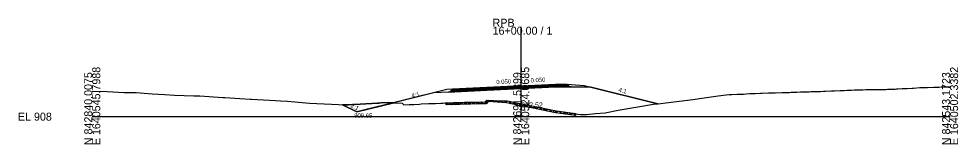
# Model space of a CAD drawing. Extents: x -26 to 1641030, y -10 to 842962.
# Drawn here: x -25.7 to 302.8, y 5990.3 to 6034.4 of the extents above; entities that cross this region are included whole.
import ezdxf

# ---------------------------------------------------------------- set-up
doc = ezdxf.new("R2010")
doc.units = 0
for name, color, linetype in [('Exist Cross Section Cell', 7, 'Continuous'), ('Exist XS Center Line Elevation Label', 7, 'Continuous'), ('Exist XS Ground Line', 7, 'Continuous'), ('Prop CMT Pvmt Course 1', 7, 'Continuous'), ('Prop CMT Pvmt Course 2', 7, 'Continuous'), ('Prop CMT Pvmt Course 3', 7, 'Continuous'), ('Prop CMT Pvmt Surface', 7, 'Continuous'), ('Prop CMT Pvmt Surface Shoulder', 7, 'Continuous'), ('Prop CMT Shld Paved Course 1', 7, 'Continuous'), ('Prop CMT Shld Paved Course 2', 7, 'Continuous'), ('Prop CMT Shld Paved Course 3', 7, 'Continuous'), ('Prop CMT Slope Grass', 7, 'Continuous'), ('Prop CMT Subgrade Earthwork', 7, 'Continuous'), ('Prop XS Ditch Standard Text', 7, 'Continuous'), ('Prop XS SE Text', 7, 'Continuous'), ('Prop XS Side Slope Text', 7, 'Continuous'), ('Prop XS Undercut Exc', 7, 'Continuous'), ('Scratch_Level_2', 7, 'Continuous'), ('Scratch_Level_3', 7, 'Continuous')]:
    doc.layers.add(name, color=color, linetype=linetype)

msp = doc.modelspace()

# ---------------------------------------------------------------- linework, layer by layer
at = {"layer": 'Exist Cross Section Cell'}
for p, q in [((150, 6000), (150, 6031.55)), ((0, 6000), (150, 6000)), ((150, 6000), (300, 6000))]:
    msp.add_line(p, q, dxfattribs=at)
at = {"layer": 'Exist XS Ground Line'}
for p, q in [((0, 6008.93), (5.2, 6008.82)), ((253.94, 6008.84), (254.69, 6008.87)), ((254.69, 6008.87), (255.74, 6008.92)), ((255.74, 6008.92), (256.47, 6008.95)), ((256.47, 6008.95), (258.57, 6009.04)), ((258.57, 6009.04), (258.99, 6009.06)), ((258.99, 6009.06), (259.55, 6009.08)), ((259.55, 6009.08), (261.52, 6009.17)), ((261.52, 6009.17), (262.98, 6009.23)), ((262.98, 6009.23), (264.04, 6009.28)), ((264.04, 6009.28), (265.47, 6009.32)), ((265.47, 6009.32), (266.57, 6009.36)), ((266.57, 6009.36), (268.43, 6009.43)), ((268.43, 6009.43), (269.1, 6009.46)), ((269.1, 6009.46), (269.53, 6009.46)), ((269.53, 6009.46), (270.59, 6009.47)), ((270.59, 6009.47), (271.62, 6009.48)), ((271.62, 6009.48), (273, 6009.5)), ((273, 6009.5), (274.35, 6009.52)), ((274.35, 6009.52), (276.68, 6009.57)), ((276.68, 6009.57), (277.54, 6009.58)), ((277.54, 6009.58), (278.16, 6009.6)), ((278.16, 6009.6), (279.07, 6009.63)), ((279.07, 6009.63), (280.84, 6009.69)), ((280.84, 6009.69), (281.29, 6009.71)), ((281.29, 6009.71), (281.73, 6009.74)), ((281.73, 6009.74), (283.23, 6009.82)), ((283.23, 6009.82), (284.26, 6009.87)), ((284.26, 6009.87), (285.02, 6009.91)), ((285.02, 6009.91), (286.78, 6010.01)), ((286.78, 6010.01), (287.23, 6010.04)), ((287.23, 6010.04), (289.4, 6010.17)), ((289.4, 6010.17), (289.73, 6010.17)), ((289.73, 6010.17), (291.45, 6010.24)), ((291.45, 6010.24), (292.11, 6010.26)), ((292.11, 6010.26), (294.36, 6010.34)), ((294.36, 6010.34), (296.04, 6010.39)), ((296.04, 6010.39), (296.89, 6010.42)), ((296.89, 6010.42), (298.03, 6010.46)), ((298.03, 6010.46), (299.42, 6010.5)), ((299.42, 6010.5), (300, 6010.52)), ((5.2, 6008.82), (11.13, 6008.51)), ((11.13, 6008.51), (15.3, 6008.45)), ((15.3, 6008.45), (20.91, 6008)), ((20.91, 6008), (25.41, 6007.81)), ((25.41, 6007.81), (28.76, 6007.49)), ((28.76, 6007.49), (35.52, 6007.35)), ((35.52, 6007.35), (37.58, 6007.25)), ((37.58, 6007.25), (45.63, 6006.72)), ((45.63, 6006.72), (46.4, 6006.68)), ((46.4, 6006.68), (51.65, 6006.35)), ((51.65, 6006.35), (55.21, 6006.12)), ((55.21, 6006.12), (55.73, 6006.09)), ((55.73, 6006.09), (64.03, 6005.67)), ((64.03, 6005.67), (65.84, 6005.55)), ((137.43, 6005.18), (138.04, 6005.75)), ((138.04, 6005.75), (140.43, 6005.68)), ((140.43, 6005.68), (145.11, 6005.5)), ((201.47, 6004.97), (210, 6006.04)), ((210, 6006.04), (214.05, 6006.6)), ((214.05, 6006.6), (218.84, 6007.27)), ((218.84, 6007.27), (221.74, 6007.67)), ((221.74, 6007.67), (222.77, 6007.74)), ((222.77, 6007.74), (223.62, 6007.79)), ((223.62, 6007.79), (225.52, 6007.87)), ((225.52, 6007.87), (226.14, 6007.89)), ((226.14, 6007.89), (227.72, 6007.94)), ((227.72, 6007.94), (228.67, 6008.01)), ((228.67, 6008.01), (229.92, 6008.09)), ((229.92, 6008.09), (231.2, 6008.14)), ((231.2, 6008.14), (231.83, 6008.16)), ((231.83, 6008.16), (233.72, 6008.22)), ((233.72, 6008.22), (234.33, 6008.24)), ((234.33, 6008.24), (236.54, 6008.3)), ((236.54, 6008.3), (238.83, 6008.36)), ((238.83, 6008.36), (241.3, 6008.43)), ((241.3, 6008.43), (241.8, 6008.44)), ((241.8, 6008.44), (243.81, 6008.5)), ((243.81, 6008.5), (244.4, 6008.54)), ((244.4, 6008.54), (245.3, 6008.56)), ((245.3, 6008.56), (246.36, 6008.6)), ((246.36, 6008.6), (247.71, 6008.65)), ((247.71, 6008.65), (248.88, 6008.69)), ((248.88, 6008.69), (250.67, 6008.74)), ((250.67, 6008.74), (251.41, 6008.77)), ((251.41, 6008.77), (253.63, 6008.83)), ((253.63, 6008.83), (253.94, 6008.84)), ((65.84, 6005.55), (68.28, 6005.38)), ((68.28, 6005.38), (75.95, 6004.78)), ((75.95, 6004.78), (83.7, 6004.4)), ((83.7, 6004.4), (88.61, 6004.14)), ((88.61, 6004.14), (89.63, 6004.15)), ((89.63, 6004.15), (99.71, 6004.74)), ((99.71, 6004.74), (100.24, 6004.77)), ((100.24, 6004.77), (100.93, 6004.81)), ((100.93, 6004.81), (103.76, 6004.97)), ((103.76, 6004.97), (104.99, 6004.9)), ((104.99, 6004.9), (105.73, 6004.85)), ((105.73, 6004.85), (108.38, 6004.68)), ((108.38, 6004.68), (108.99, 6004.16)), ((108.99, 6004.16), (110.81, 6004.21)), ((110.81, 6004.21), (112.44, 6004.31)), ((112.44, 6004.31), (114.5, 6004.42)), ((114.5, 6004.42), (114.97, 6004.44)), ((114.97, 6004.44), (117.68, 6004.56)), ((117.68, 6004.56), (120.02, 6004.65)), ((120.02, 6004.65), (121.93, 6004.73)), ((121.93, 6004.73), (122.55, 6004.76)), ((122.55, 6004.76), (123.35, 6004.79)), ((123.35, 6004.79), (123.76, 6004.81)), ((123.76, 6004.81), (125.08, 6004.86)), ((125.08, 6004.86), (126.34, 6004.91)), ((126.34, 6004.91), (127.6, 6004.95)), ((127.6, 6004.95), (128.54, 6004.98)), ((128.54, 6004.98), (130.13, 6005.03)), ((130.13, 6005.03), (132.27, 6005.07)), ((132.27, 6005.07), (132.66, 6005.08)), ((132.66, 6005.08), (135.44, 6005.13)), ((135.44, 6005.13), (137.43, 6005.18)), ((145.11, 6005.5), (150.06, 6004.51)), ((150.06, 6004.51), (154.86, 6003.56)), ((154.86, 6003.56), (162.19, 6002.03)), ((183.94, 6002.27), (196.28, 6004.32)), ((196.28, 6004.32), (197.91, 6004.52)), ((197.91, 6004.52), (201.47, 6004.97)), ((162.19, 6002.03), (170.8, 6000.81)), ((170.8, 6000.81), (171.78, 6000.76)), ((171.78, 6000.76), (172.16, 6000.76)), ((172.16, 6000.76), (172.84, 6000.75)), ((172.84, 6000.75), (176.02, 6001.05)), ((176.02, 6001.05), (179.43, 6001.38)), ((179.43, 6001.38), (183.94, 6002.27))]:
    msp.add_line(p, q, dxfattribs=at)
at = {"layer": 'Prop CMT Pvmt Course 1'}
for points in [[(150, 6010.81), (138.01, 6010.21)], [(138.01, 6009.96), (150, 6010.56)], [(138.01, 6010.21), (138.01, 6009.96)], [(150, 6010.81), (162.01, 6011.41)], [(162.01, 6011.16), (150, 6010.56)], [(150, 6010.56), (150, 6010.81)], [(150, 6010.56), (150, 6010.81)], [(162.01, 6011.41), (162.01, 6011.16)]]:
    msp.add_lwpolyline(points, dxfattribs=at)
msp.add_lwpolyline([(150, 6010.56), (150, 6010.69), (150, 6010.69), (150, 6010.56)], close=True, dxfattribs=at)
msp.add_lwpolyline([(150, 6010.56), (150, 6010.69), (150, 6010.69), (150, 6010.56)], close=True, dxfattribs=at)
at = {"layer": 'Prop CMT Pvmt Course 2'}
for p in [(138.01, 6009.63), (162.01, 6010.83)]:
    msp.add_line(p, (150, 6010.23), dxfattribs=at)
for points in [[(150, 6010.56), (138.01, 6009.96)], [(138.01, 6009.96), (138.01, 6009.63)], [(150, 6010.56), (162.01, 6011.16)], [(150, 6010.31), (150, 6010.56)], [(150, 6010.31), (150, 6010.56)], [(162.01, 6011.16), (162.01, 6010.83)]]:
    msp.add_lwpolyline(points, dxfattribs=at)
at = {"layer": 'Prop CMT Pvmt Course 3'}
for p, q in [((150, 6010.23), (138.01, 6009.63)), ((138.01, 6009.3), (150, 6009.89)), ((150, 6010.23), (162.01, 6010.83)), ((162.01, 6010.5), (150, 6009.89))]:
    msp.add_line(p, q, dxfattribs=at)
for points in [[(138.01, 6009.63), (138.01, 6009.3)], [(150, 6009.94), (150, 6010.31)], [(150, 6009.94), (150, 6010.31)], [(162.01, 6010.83), (162.01, 6010.5)]]:
    msp.add_lwpolyline(points, dxfattribs=at)
at = {"layer": 'Prop CMT Pvmt Surface'}
for points in [[(150, 6010.81), (138.01, 6010.21)], [(150, 6010.81), (162.01, 6011.41)]]:
    msp.add_lwpolyline(points, dxfattribs=at)
at = {"layer": 'Prop CMT Pvmt Surface Shoulder'}
for points in [[(138.01, 6010.21), (126.01, 6009.61)], [(162.01, 6011.41), (166.01, 6011.37)]]:
    msp.add_lwpolyline(points, dxfattribs=at)
at = {"layer": 'Prop CMT Shld Paved Course 1'}
for points in [[(138.01, 6010.21), (126.01, 6009.61), (125.74, 6009.35)], [(125.74, 6009.35), (138.01, 6009.96)], [(138.01, 6009.96), (138.01, 6010.21)], [(162.01, 6011.41), (166.01, 6011.37), (166.26, 6011.12)], [(162.01, 6011.16), (162.01, 6011.41)], [(166.26, 6011.12), (162.01, 6011.16)]]:
    msp.add_lwpolyline(points, dxfattribs=at)
at = {"layer": 'Prop CMT Shld Paved Course 2'}
for p, q in [((125.39, 6009), (138.01, 6009.63)), ((125.74, 6009.35), (125.39, 6009)), ((138.01, 6009.96), (125.74, 6009.35)), ((162.01, 6011.16), (166.26, 6011.12)), ((166.6, 6010.78), (162.01, 6010.83)), ((166.26, 6011.12), (166.6, 6010.78))]:
    msp.add_line(p, q, dxfattribs=at)
for points in [[(138.01, 6009.71), (138.01, 6009.96)], [(162.01, 6010.83), (162.01, 6011.16)]]:
    msp.add_lwpolyline(points, dxfattribs=at)
at = {"layer": 'Prop CMT Shld Paved Course 3'}
for p, q in [((124.54, 6008.62), (138.01, 6009.3)), ((125.39, 6009), (125.04, 6008.65)), ((138.01, 6009.63), (125.48, 6009)), ((162.01, 6010.83), (166.51, 6010.78)), ((167.43, 6010.44), (162.01, 6010.5)), ((166.6, 6010.78), (166.93, 6010.45))]:
    msp.add_line(p, q, dxfattribs=at)
for points in [[(138.01, 6009.34), (138.01, 6009.63)], [(162.01, 6010.5), (162.01, 6010.83)]]:
    msp.add_lwpolyline(points, dxfattribs=at)
at = {"layer": 'Prop CMT Slope Grass'}
msp.add_line((126.01, 6009.61), (124.01, 6009.51), dxfattribs=at)
for points in [[(124.01, 6009.51), (92.56, 6001.65)], [(166.01, 6011.37), (172.01, 6010.95), (197.79, 6004.51)], [(92.56, 6001.65), (87.46, 6004.2)]]:
    msp.add_lwpolyline(points, dxfattribs=at)
at = {"layer": 'Prop CMT Subgrade Earthwork'}
for p, q in [((138.01, 6009.3), (124.54, 6008.62)), ((150, 6009.89), (138.01, 6009.3)), ((150, 6009.89), (162.01, 6010.5)), ((162.01, 6010.5), (167.43, 6010.44)), ((167.43, 6010.44), (174.32, 6010.37)), ((124.54, 6008.62), (119.43, 6008.37))]:
    msp.add_line(p, q, dxfattribs=at)
at = {"layer": 'Prop XS Undercut Exc'}
for p, q in [((137.14, 6004.51), (138.38, 6005.74)), ((137.43, 6005.18), (138.04, 6005.75)), ((138.04, 6005.75), (140.43, 6005.68)), ((138.24, 6005.75), (138.74, 6005.24)), ((139.26, 6005.21), (139.75, 6005.7)), ((139.7, 6005.7), (140.25, 6005.15)), ((140.43, 6005.68), (145.11, 6005.5)), ((140.59, 6005.12), (141.12, 6005.65)), ((141.16, 6005.65), (141.77, 6005.05)), ((141.92, 6005.04), (142.48, 6005.6)), ((142.63, 6005.6), (143.28, 6004.95)), ((123.7, 6004.81), (130.13, 6005.03)), ((123.73, 6004.14), (123.7, 6004.81)), ((123.7, 6004.72), (124.27, 6004.16)), ((126.37, 6004.24), (123.73, 6004.14)), ((124.06, 6004.15), (124.75, 6004.84)), ((124.99, 6004.85), (125.63, 6004.21)), ((125.53, 6004.2), (126.22, 6004.89)), ((126.36, 6004.9), (127, 6004.26)), ((127.63, 6004.28), (126.37, 6004.24)), ((127, 6004.26), (127.68, 6004.94)), ((128.56, 6004.31), (127.63, 6004.28)), ((127.73, 6004.94), (128.37, 6004.31)), ((128.46, 6004.31), (129.15, 6004.99)), ((130.14, 6004.36), (128.56, 6004.31)), ((129.1, 6004.99), (129.74, 6004.35)), ((129.92, 6004.35), (130.6, 6005.04)), ((130.13, 6005.03), (132.66, 6005.08)), ((132.28, 6004.4), (130.14, 6004.36)), ((130.47, 6005.03), (131.12, 6004.38)), ((131.36, 6004.38), (132.04, 6005.06)), ((131.86, 6005.06), (132.51, 6004.4)), ((135.46, 6004.46), (132.28, 6004.4)), ((132.66, 6005.08), (137.43, 6005.18)), ((132.8, 6004.41), (133.49, 6005.09)), ((133.24, 6005.09), (133.9, 6004.43)), ((134.25, 6004.44), (134.93, 6005.12)), ((134.63, 6005.12), (135.28, 6004.46)), ((137.7, 6004.52), (135.46, 6004.46)), ((135.69, 6004.47), (136.38, 6005.16)), ((136.01, 6005.15), (136.66, 6004.49)), ((137.39, 6005.18), (137.88, 6004.69)), ((138.5, 6005.26), (137.7, 6004.52)), ((145.02, 6004.84), (138.5, 6005.26)), ((143.25, 6004.95), (143.85, 6005.55)), ((144.1, 6005.54), (144.79, 6004.85)), ((144.58, 6004.87), (145.19, 6005.49)), ((149.93, 6003.85), (145.02, 6004.84)), ((145.11, 6005.5), (154.86, 6003.56)), ((145.66, 6005.39), (146.52, 6004.54)), ((145.8, 6004.68), (146.37, 6005.25)), ((146.98, 6004.44), (147.55, 6005.02)), ((147.43, 6005.04), (148.29, 6004.18)), ((148.16, 6004.21), (148.73, 6004.78)), ((149.19, 6004.69), (150.06, 6003.83)), ((149.34, 6003.97), (149.91, 6004.55)), ((154.73, 6002.91), (149.93, 6003.85)), ((150.52, 6003.74), (151.09, 6004.31)), ((150.96, 6004.34), (151.82, 6003.48)), ((151.7, 6003.5), (152.27, 6004.08)), ((152.73, 6003.99), (153.58, 6003.13)), ((152.88, 6003.27), (153.45, 6003.84)), ((154.06, 6003.04), (154.63, 6003.61)), ((154.49, 6003.64), (155.35, 6002.78)), ((162.05, 6001.37), (154.73, 6002.91)), ((154.86, 6003.56), (162.19, 6002.03)), ((155.24, 6002.8), (155.8, 6003.37)), ((156.27, 6003.27), (157.14, 6002.4)), ((156.41, 6002.56), (156.97, 6003.12)), ((157.58, 6002.31), (158.14, 6002.88)), ((158.06, 6002.89), (158.93, 6002.03)), ((158.74, 6002.06), (159.31, 6002.63)), ((159.85, 6002.52), (160.72, 6001.65)), ((159.91, 6001.82), (160.48, 6002.39)), ((161.08, 6001.57), (161.65, 6002.14)), ((161.64, 6002.14), (162.47, 6001.31)), ((169.01, 6000.39), (162.05, 6001.37)), ((162.19, 6002.03), (168.97, 6001.07)), ((162.26, 6001.34), (162.85, 6001.93)), ((163.33, 6001.87), (164.12, 6001.08)), ((163.5, 6001.17), (164.09, 6001.76)), ((164.74, 6000.99), (165.33, 6001.58)), ((164.98, 6001.63), (165.77, 6000.85)), ((165.98, 6000.82), (166.57, 6001.41)), ((166.63, 6001.4), (167.41, 6000.61)), ((167.22, 6000.64), (167.81, 6001.23)), ((168.27, 6001.17), (169.01, 6000.43)), ((168.46, 6000.47), (168.98, 6000.99)), ((168.97, 6001.07), (169.01, 6000.39))]:
    msp.add_line(p, q, dxfattribs=at)
at = {"layer": 'Scratch_Level_2'}
for p, q in [((87.46, 6004.2), (92.56, 6001.65)), ((92.56, 6001.65), (105.44, 6004.87))]:
    msp.add_line(p, q, dxfattribs=at)
msp.add_lwpolyline([(105.44, 6004.87), (104.99, 6004.9), (103.76, 6004.97), (100.93, 6004.81), (100.24, 6004.77), (99.71, 6004.74), (89.63, 6004.15), (88.61, 6004.14), (87.46, 6004.2)], dxfattribs=at)
at = {"layer": 'Scratch_Level_3'}
for p, q in [((138.01, 6009.3), (124.54, 6008.62)), ((150, 6009.89), (138.01, 6009.3)), ((162.01, 6010.5), (150, 6009.89)), ((167.43, 6010.44), (162.01, 6010.5)), ((174.32, 6010.37), (167.43, 6010.44)), ((197.78, 6004.51), (174.32, 6010.37)), ((119.43, 6008.37), (105.44, 6004.87)), ((124.54, 6008.62), (119.43, 6008.37))]:
    msp.add_line(p, q, dxfattribs=at)
msp.add_lwpolyline([(105.44, 6004.87), (105.73, 6004.85), (108.38, 6004.68), (108.99, 6004.16), (110.81, 6004.21), (112.44, 6004.31), (114.5, 6004.42), (114.97, 6004.44), (117.68, 6004.56), (120.02, 6004.65), (121.93, 6004.73), (122.55, 6004.76), (123.35, 6004.79), (123.76, 6004.81), (125.08, 6004.86), (126.34, 6004.91), (127.6, 6004.95), (128.54, 6004.98), (130.13, 6005.03), (132.27, 6005.07), (132.66, 6005.08), (135.44, 6005.13), (137.43, 6005.18), (138.04, 6005.75), (140.43, 6005.68), (145.11, 6005.5), (150.06, 6004.51), (154.86, 6003.56), (162.19, 6002.03), (170.8, 6000.81), (171.78, 6000.76), (172.16, 6000.76), (172.84, 6000.75), (176.02, 6001.05), (179.43, 6001.38), (183.94, 6002.27), (196.28, 6004.32), (197.78, 6004.51)], dxfattribs=at)

# ---------------------------------------------------------------- texts
at = {"layer": 'Exist Cross Section Cell'}
for s, p in [('RPB', (140, 6031.55)), ('16+00.00 / 1', (140, 6028.75)), ('EL 908', (-26, 5998.6))]:
    msp.add_text(s, height=2.8, dxfattribs=at).set_placement(p)
for s, p in [('N 842840.0075', (0, 5990)), ('E 1640545.7988', (2.8, 5990)), ('E 1640524.0685', (152.8, 5990)), ('N 842543.1723', (300, 5990)), ('E 1640502.3382', (302.8, 5990)), ('N 842691.5899', (150, 5990))]:
    msp.add_text(s, height=2.8, rotation=90, dxfattribs=at).set_placement(p)
at = {"layer": 'Exist XS Center Line Elevation Label'}
msp.add_text('912.52', height=1.8, dxfattribs=at).set_placement((150, 6003.22))
at = {"layer": 'Prop XS Ditch Standard Text'}
msp.add_text('909.65', height=1.5, dxfattribs=at).set_placement((91.62, 5999.64))
at = {"layer": 'Prop XS SE Text'}
for p in [(141.33, 6011.38), (153.33, 6011.98)]:
    msp.add_text('0.050', height=1.5, rotation=2.8624, dxfattribs=at).set_placement(p)
at = {"layer": 'Prop XS Side Slope Text'}
for s, rotation, p in [('4:1', 345.9638, (183.92, 6008.74)), ('4:1', 14.0362, (111.82, 6006.6)), ('2:1', 333.4349, (90.22, 6003.41))]:
    msp.add_text(s, height=1.5, rotation=rotation, dxfattribs=at).set_placement(p)

doc.saveas('drawing.dxf')
